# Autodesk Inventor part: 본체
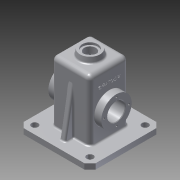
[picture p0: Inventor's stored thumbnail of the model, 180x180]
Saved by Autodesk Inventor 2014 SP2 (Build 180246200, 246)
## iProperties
Created: 2016-02
Part Number: 본체
Material: 알루미늄 6061
Document SubType Name: Modeling
Designer: apexhp001
Density: 2.71 g/cm^3
Appearance: 알루미늄 - 평지
Mass: 932.811 g
Surface Area: 1043.48 cm^2
Volume: 344.211 cm^3
Author: apexhp001
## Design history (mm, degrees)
sketch "스케치1"
  geometry: L1 (-35, 35)-(35, 35); L2 (35, 35)-(35, -35); L3 (35, -35)-(-35, -35); L4 (-35, -35)-(-35, 35); L5 (-35, 35)-(35, -35); L6 (35, 35)-(-35, -35); 1 further point
  constraints: 12 end point, 2 midpoint, 2 parallel, 1 horizontal, 1 perpendicular
  dimensions: "d0" = 70 distance of L1.start L1.end; "d1" = 70 distance of L1.end L2.end
extrude "돌출1" new body sketch "스케치1" distance "d2" = 120; taper "d3" = 0 deg
fillet "모깎기1" dims "d4" = 8
feature "쉘1" dims "d5" = 5
sketch "스케치2"
  geometry: L1 (27, 35)-(-27, 35) reference; L2 (-35, 27)-(-35, -27) reference; L3 (-27, -35)-(27, -35) reference; L4 (35, -27)-(35, 27) reference; L5 (-65, 65)-(65, 65); L6 (65, 65)-(65, -65); L7 (65, -65)-(-65, -65); L8 (-65, -65)-(-65, 65); L9 (-65, 65)-(65, -65); L10 (65, 65)-(-65, -65); A1 r 8 centre (27, 27) between (35, 27) and (27, 35) reference; A2 r 8 centre (-27, 27) between (-27, 35) and (-35, 27) reference; A3 r 8 centre (-27, -27) between (-35, -27) and (-27, -35) reference; A4 r 8 centre (27, -27) between (27, -35) and (35, -27) reference; 1 further point
  constraints: 12 end point, 2 midpoint, 2 parallel, 1 horizontal, 1 perpendicular
  dimensions: "d6" = 130 distance of L5.start L5.end; "d7" = 130 distance of L5.end L6.end
extrude "돌출2" join sketch "스케치2" distance "d8" = 10; taper "d9" = 0 deg
sketch "스케치3"
  geometry: L1 (30, 0)-(30, 112) reference; L2 (48, 55)-(0, 55); L3 (23, 75.5)-(30, 82.5); L4 (30, 82.5)-(48, 82.5); L5 (48, 82.5)-(48, 55); L6 (23, 75.5)-(23, 55); L7 (35, 10)-(35, 112) reference; 1 further point
  constraints: 10 end point, 3 perpendicular, 2 point on line, 1 parallel, 1 vertical alignment
  dimensions: "d10" = 55 distance of point (0, 0) L2.end; "d11" = 135 deg angle of L1 L3; "d13" = 7 distance between parallel lines of L6 L1; "d14" = 13 distance from line of L7 L4.end; "d15" = 55 diameter of L4 L2
revolve "회전1" sketch "스케치3" stored, may be unused: angle "d16" = 90 deg
sketch "스케치4"
  geometry: C1 r 27.5 at (0, 0) reference; C2 r 16 at (0, 0); 1 further point
  constraints: 1 centre point, 1 coincident
  dimensions: "d17" = 32 diameter of C2
extrude "돌출3" cut sketch "스케치4" stored distance "d18" = 10; taper "d19" = 0 deg
sketch "스케치5"
  geometry: C1 r 16 at (0, 0) reference; 2 further points
  constraints: 1 horizontal alignment
  dimensions: "d20" = 22.5 distance of C1.centre point (-22.5, 0)
hole "구멍1" sketch "스케치5" at (-22.5, 0) diameter "d21" = 3.242; stored, may be unused: countersink angle "d25" = 90 deg, drill point angle "d27" = 118 deg; dims "d22" = 8, "d23" = 4, "d24" = 2, "d26" = 10
sketch "스케치6"
  geometry: C1 r 20 at (0, 0); 1 further point
  constraints: 1 centre point, 1 coincident
  dimensions: "d31" = 40 diameter of C1
extrude "돌출4" join sketch "스케치6" distance "d32" = 10; taper "d33" = -10 deg
hole "구멍2" diameter "d36" = 21; stored, may be unused: countersink angle "d40" = 90 deg, drill point angle "d42" = 118 deg; dims "d34" = 10, "d35" = 10, "d37" = 8, "d38" = 28, "d39" = 4, "d41" = 10
sketch "스케치7"
  geometry: L1 (-35, 10)-(-35, 112) reference; L2 (65, 10)-(-65, 10) reference; L3 (35, 112)-(35, 10) reference; L4 (50, 10)-(35, 95.069); L5 (-50, 10)-(-35, 95.069); L6 (65, 0)-(65, 10) reference; 1 further point
  constraints: 4 end point, 4 point on line, 1 equal length
  dimensions: "d43" = 15 distance of L4.start L2.start; "d44" = 10 deg angle of L6 L4; "d45" = 15 distance of L5.start L2.end
extrude "돌출5" join sketch "스케치7" stored distance "d46" = 10; taper "d47" = 0 deg
sketch "스케치8"
  geometry: L1 (-50, 50)-(50, 50); L2 (50, 50)-(50, -50); L3 (50, -50)-(-50, -50); L4 (-50, -50)-(-50, 50); L5 (-50, 50)-(50, -50); L6 (50, 50)-(-50, -50); 1 further point
  constraints: 12 end point, 2 midpoint, 2 parallel, 1 horizontal, 1 perpendicular
  dimensions: "d48" = 100 distance of L1.start L1.end; "d49" = 100 distance of L1.end L2.end
hole "구멍3" sketch "스케치8" at (-50, -50), (50, -50), (50, 50), (-50, 50) diameter "d50" = 12; stored, may be unused: countersink angle "d54" = 90 deg, drill point angle "d56" = 118 deg; dims "d51" = 8, "d52" = 28, "d53" = 4, "d55" = 10
chamfer "모따기1" distance "d57" = 10; stored, may be unused: second distance "d58" = 2, angle "d59" = 45 deg
sketch "스케치9"
  geometry: L1 (-18, 8.763)-(-18, 45.237) reference; L2 (102, 62)-(0, 62) reference; 2 further points
  constraints: 1 other
  dimensions: "d60" = 35 distance from line of point (17, 27) L1; "d61" = 35 distance from line of point (17, 27) L2
feature "엠보싱1" sketch "스케치9" dims "d0" = 70, "d1" = 70, "d62" = 0.5, "d63" = 0
chamfer "모따기2" distance "d64" = 1; stored, may be unused: second distance "d65" = 2, angle "d66" = 45 deg
fillet "모깎기2" dims "d67" = 3
fillet "모깎기3" dims "d68" = 3
fillet "모깎기4" dims "d69" = 0.5
fillet "모깎기5" dims "d70" = 3
node "솔리드1"
mirror "대칭1"
pattern_circular "원형 패턴1" dims angle "d29" = 360 deg
mirror "대칭2"
